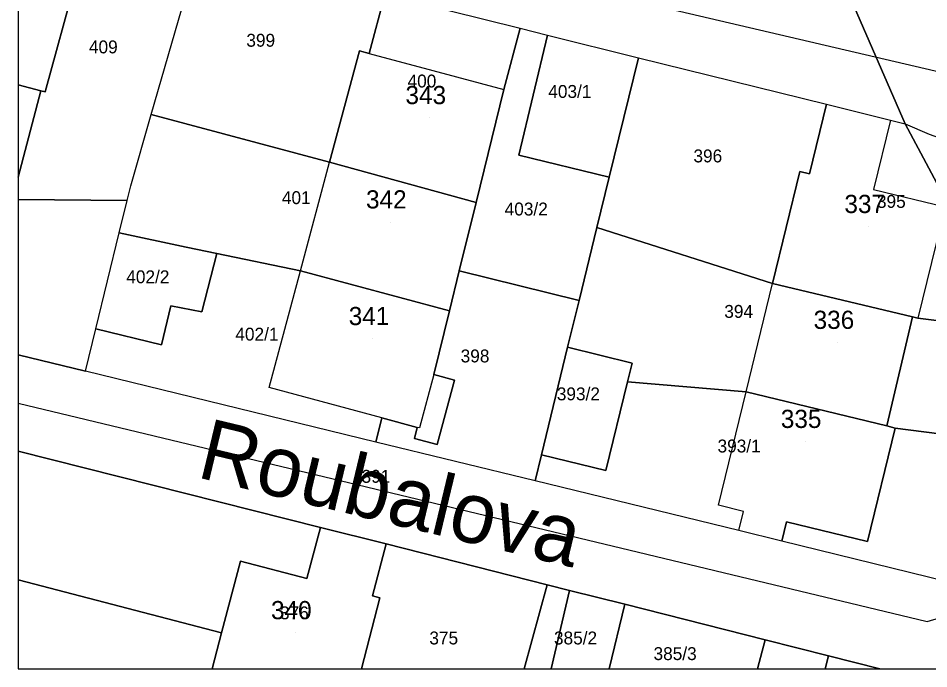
# Model space of a CAD drawing. Extents: x -873642 to -872917, y -1012962 to -1012567.
# Drawn here: x -873642.3 to -873582.3, y -1012961.7 to -1012918.8 of the extents above; entities that cross this region are included whole.
import ezdxf

# ---------------------------------------------------------------- set-up
doc = ezdxf.new("R2010")
doc.units = 0
for name, color, linetype in [('adresni_misto', 7, 'Continuous'), ('cisla_parcelni_kn', 7, 'Continuous'), ('cislo_domovni', 7, 'Continuous'), ('osy_ulic', 7, 'Continuous'), ('parcely_kn', 7, 'Continuous'), ('stavebni_objekty_bydleni', 7, 'Continuous'), ('stavebni_objekty_ostatni', 7, 'Continuous'), ('ulice', 7, 'Continuous')]:
    doc.layers.add(name, color=color, linetype=linetype)

msp = doc.modelspace()

# ---------------------------------------------------------------- linework, layer by layer
at = {"layer": 'adresni_misto'}
for p, q in [((-873615.17, -1012925.36), (-873615.17, -1012925.36)), ((-873617.77, -1012932.24), (-873617.77, -1012932.24)), ((-873586.24, -1012932.54), (-873586.24, -1012932.54)), ((-873618.91, -1012939.93), (-873618.91, -1012939.93)), ((-873588.27, -1012940.18), (-873588.27, -1012940.18)), ((-873590.43, -1012946.71), (-873590.43, -1012946.71)), ((-873624.03, -1012959.32), (-873624.03, -1012959.32))]:
    msp.add_line(p, q, dxfattribs=at)
at = {"layer": 'osy_ulic'}
for points in [[(-873642.294, -1012908.128), (-873579.23, -1012922.87)], [(-873642.294, -1012944.182), (-873582.38, -1012958.56), (-873564.82, -1012953.34)]]:
    msp.add_lwpolyline(points, dxfattribs=at)
at = {"layer": 'parcely_kn'}
for p, q in [((-873642.294, -1012910.954), (-873642.294, -1012923.197)), ((-873642.294, -1012910.954), (-873642.294, -1012923.197)), ((-873642.294, -1012923.197), (-873642.294, -1012929.279)), ((-873642.294, -1012923.197), (-873642.294, -1012929.279)), ((-873642.294, -1012929.279), (-873642.294, -1012930.754)), ((-873642.294, -1012929.279), (-873642.294, -1012930.754)), ((-873642.294, -1012930.754), (-873642.294, -1012940.985)), ((-873642.294, -1012930.754), (-873642.294, -1012940.985)), ((-873642.294, -1012940.985), (-873642.294, -1012947.334)), ((-873642.294, -1012940.985), (-873642.294, -1012947.334)), ((-873642.294, -1012947.334), (-873642.294, -1012955.815)), ((-873642.294, -1012947.334), (-873642.294, -1012955.815)), ((-873629.511, -1012961.688), (-873619.678, -1012961.688)), ((-873629.511, -1012961.688), (-873619.678, -1012961.688)), ((-873619.678, -1012961.688), (-873608.948, -1012961.688)), ((-873619.678, -1012961.688), (-873608.948, -1012961.688)), ((-873608.948, -1012961.688), (-873607.163, -1012961.688)), ((-873608.948, -1012961.688), (-873607.163, -1012961.688)), ((-873607.163, -1012961.688), (-873603.346, -1012961.688)), ((-873607.163, -1012961.688), (-873603.346, -1012961.688)), ((-873603.346, -1012961.688), (-873593.567, -1012961.688)), ((-873603.346, -1012961.688), (-873593.567, -1012961.688)), ((-873593.567, -1012961.688), (-873589.111, -1012961.688)), ((-873593.567, -1012961.688), (-873589.111, -1012961.688)), ((-873589.111, -1012961.688), (-873585.502, -1012961.688)), ((-873589.111, -1012961.688), (-873585.502, -1012961.688)), ((-873585.502, -1012961.688), (-873575.538, -1012961.688)), ((-873585.502, -1012961.688), (-873575.538, -1012961.688))]:
    msp.add_line(p, q, dxfattribs=at)
for points in [[(-873605.78, -1012857.48), (-873599.19, -1012877.96), (-873591.75, -1012899.33), (-873585.82, -1012914.89), (-873585.57, -1012916.87), (-873587.17, -1012918.1), (-873583.83, -1012925.76), (-873582.25, -1012926.45), (-873580.53, -1012927.05), (-873570.45, -1012948.46), (-873570.98, -1012949.83), (-873566.12, -1012958.98), (-873564.03, -1012959.51), (-873563.08, -1012960.39), (-873562.393, -1012961.688)], [(-873605.78, -1012857.48), (-873599.19, -1012877.96), (-873591.75, -1012899.33), (-873585.82, -1012914.89), (-873585.57, -1012916.87), (-873587.17, -1012918.1), (-873583.83, -1012925.76), (-873582.25, -1012926.45), (-873580.53, -1012927.05), (-873570.45, -1012948.46), (-873570.98, -1012949.83), (-873566.12, -1012958.98), (-873564.03, -1012959.51), (-873563.08, -1012960.39), (-873562.393, -1012961.688)], [(-873642.294, -1012910.954), (-873642.19, -1012910.98), (-873637.42, -1012912.31), (-873630.37, -1012914.2), (-873618.13, -1012917.24), (-873613.91, -1012918.29), (-873609.21, -1012919.46), (-873607.41, -1012919.91), (-873601.41, -1012921.4), (-873589.03, -1012924.47), (-873584.8, -1012925.52), (-873583.83, -1012925.76), (-873587.17, -1012918.1), (-873591.39, -1012918.13), (-873606.87, -1012914.13), (-873624.13, -1012909.67), (-873628.43, -1012908.7), (-873632.49, -1012907.8), (-873634.32, -1012907.21), (-873639.87, -1012905.77), (-873642.294, -1012905.138)], [(-873642.294, -1012910.954), (-873642.19, -1012910.98), (-873637.42, -1012912.31), (-873630.37, -1012914.2), (-873618.13, -1012917.24), (-873613.91, -1012918.29), (-873609.21, -1012919.46), (-873607.41, -1012919.91), (-873601.41, -1012921.4), (-873589.03, -1012924.47), (-873584.8, -1012925.52), (-873583.83, -1012925.76), (-873587.17, -1012918.1), (-873591.39, -1012918.13), (-873606.87, -1012914.13), (-873624.13, -1012909.67), (-873628.43, -1012908.7), (-873632.49, -1012907.8), (-873634.32, -1012907.21), (-873639.87, -1012905.77), (-873642.294, -1012905.138)], [(-873642.294, -1012923.197), (-873640.8, -1012923.59), (-873640.52, -1012923.65), (-873638.51, -1012916.34), (-873637.42, -1012912.31), (-873642.19, -1012910.98), (-873642.294, -1012910.954)], [(-873642.294, -1012923.197), (-873640.8, -1012923.59), (-873640.52, -1012923.65), (-873638.51, -1012916.34), (-873637.42, -1012912.31), (-873642.19, -1012910.98), (-873642.294, -1012910.954)], [(-873642.294, -1012930.754), (-873635.11, -1012930.82), (-873634.87, -1012929.85), (-873633.52, -1012925.14), (-873630.37, -1012914.2), (-873637.42, -1012912.31), (-873638.51, -1012916.34), (-873640.52, -1012923.65), (-873640.8, -1012923.59), (-873642.294, -1012929.279)], [(-873642.294, -1012930.754), (-873635.11, -1012930.82), (-873634.87, -1012929.85), (-873633.52, -1012925.14), (-873630.37, -1012914.2), (-873637.42, -1012912.31), (-873638.51, -1012916.34), (-873640.52, -1012923.65), (-873640.8, -1012923.59), (-873642.294, -1012929.279)], [(-873642.294, -1012929.279), (-873640.8, -1012923.59), (-873642.294, -1012923.197)], [(-873642.294, -1012929.279), (-873640.8, -1012923.59), (-873642.294, -1012923.197)], [(-873642.294, -1012940.985), (-873637.85, -1012942.07), (-873637.17, -1012939.28), (-873635.63, -1012932.95), (-873635.11, -1012930.82), (-873642.294, -1012930.754)], [(-873642.294, -1012940.985), (-873637.85, -1012942.07), (-873637.17, -1012939.28), (-873635.63, -1012932.95), (-873635.11, -1012930.82), (-873642.294, -1012930.754)], [(-873575.538, -1012961.688), (-873570.25, -1012959.15), (-873566.12, -1012958.98), (-873570.98, -1012949.83), (-873579.87, -1012956.23), (-873591.97, -1012953.27), (-873594.79, -1012952.58), (-873608.23, -1012949.3), (-873618.72, -1012946.74), (-873637.85, -1012942.07), (-873642.294, -1012940.985)], [(-873575.538, -1012961.688), (-873570.25, -1012959.15), (-873566.12, -1012958.98), (-873570.98, -1012949.83), (-873579.87, -1012956.23), (-873591.97, -1012953.27), (-873594.79, -1012952.58), (-873608.23, -1012949.3), (-873618.72, -1012946.74), (-873637.85, -1012942.07), (-873642.294, -1012940.985)], [(-873642.294, -1012947.334), (-873622.38, -1012952.37), (-873618.05, -1012953.46), (-873607.42, -1012956.15), (-873605.95, -1012956.52), (-873602.32, -1012957.43), (-873593.07, -1012959.77), (-873588.89, -1012960.83), (-873585.502, -1012961.688)], [(-873642.294, -1012955.815), (-873628.89, -1012959.32), (-873627.65, -1012954.59), (-873623.26, -1012955.74), (-873622.38, -1012952.37), (-873642.294, -1012947.334)], [(-873642.294, -1012947.334), (-873622.38, -1012952.37), (-873618.05, -1012953.46), (-873607.42, -1012956.15), (-873605.95, -1012956.52), (-873602.32, -1012957.43), (-873593.07, -1012959.77), (-873588.89, -1012960.83), (-873585.502, -1012961.688)], [(-873642.294, -1012955.815), (-873628.89, -1012959.32), (-873627.65, -1012954.59), (-873623.26, -1012955.74), (-873622.38, -1012952.37), (-873642.294, -1012947.334)], [(-873619.678, -1012961.688), (-873618.46, -1012957), (-873618.94, -1012956.87), (-873618.05, -1012953.46), (-873622.38, -1012952.37), (-873623.26, -1012955.74), (-873627.65, -1012954.59), (-873628.89, -1012959.32), (-873629.511, -1012961.688)], [(-873619.678, -1012961.688), (-873618.46, -1012957), (-873618.94, -1012956.87), (-873618.05, -1012953.46), (-873622.38, -1012952.37), (-873623.26, -1012955.74), (-873627.65, -1012954.59), (-873628.89, -1012959.32), (-873629.511, -1012961.688)], [(-873608.948, -1012961.688), (-873607.42, -1012956.15), (-873618.05, -1012953.46), (-873618.94, -1012956.87), (-873618.46, -1012957), (-873619.678, -1012961.688)], [(-873608.948, -1012961.688), (-873607.42, -1012956.15), (-873618.05, -1012953.46), (-873618.94, -1012956.87), (-873618.46, -1012957), (-873619.678, -1012961.688)], [(-873642.294, -1012955.815), (-873642.294, -1012961.688), (-873629.511, -1012961.688)], [(-873629.511, -1012961.688), (-873628.89, -1012959.32), (-873642.294, -1012955.815)], [(-873642.294, -1012955.815), (-873642.294, -1012961.688), (-873629.511, -1012961.688)], [(-873629.511, -1012961.688), (-873628.89, -1012959.32), (-873642.294, -1012955.815)], [(-873607.163, -1012961.688), (-873605.95, -1012956.52), (-873607.42, -1012956.15), (-873608.948, -1012961.688)], [(-873607.163, -1012961.688), (-873605.95, -1012956.52), (-873607.42, -1012956.15), (-873608.948, -1012961.688)], [(-873603.346, -1012961.688), (-873602.32, -1012957.43), (-873605.95, -1012956.52), (-873607.163, -1012961.688)], [(-873603.346, -1012961.688), (-873602.32, -1012957.43), (-873605.95, -1012956.52), (-873607.163, -1012961.688)], [(-873593.567, -1012961.688), (-873593.07, -1012959.77), (-873602.32, -1012957.43), (-873603.346, -1012961.688)], [(-873593.567, -1012961.688), (-873593.07, -1012959.77), (-873602.32, -1012957.43), (-873603.346, -1012961.688)], [(-873589.111, -1012961.688), (-873588.89, -1012960.83), (-873593.07, -1012959.77), (-873593.567, -1012961.688)], [(-873589.111, -1012961.688), (-873588.89, -1012960.83), (-873593.07, -1012959.77), (-873593.567, -1012961.688)], [(-873585.502, -1012961.688), (-873588.89, -1012960.83), (-873589.111, -1012961.688)], [(-873585.502, -1012961.688), (-873588.89, -1012960.83), (-873589.111, -1012961.688)]]:
    msp.add_lwpolyline(points, dxfattribs=at)
for points in [[(-873633.52, -1012925.14), (-873630.37, -1012914.2), (-873618.13, -1012917.24), (-873619.17, -1012921.12), (-873619.8, -1012920.95), (-873621.77, -1012928.29)], [(-873633.52, -1012925.14), (-873630.37, -1012914.2), (-873618.13, -1012917.24), (-873619.17, -1012921.12), (-873619.8, -1012920.95), (-873621.77, -1012928.29)], [(-873619.8, -1012920.95), (-873619.17, -1012921.12), (-873618.13, -1012917.24), (-873613.91, -1012918.29), (-873609.21, -1012919.46), (-873610.29, -1012923.5), (-873612.11, -1012930.94), (-873621.77, -1012928.29)], [(-873619.8, -1012920.95), (-873619.17, -1012921.12), (-873618.13, -1012917.24), (-873613.91, -1012918.29), (-873609.21, -1012919.46), (-873610.29, -1012923.5), (-873612.11, -1012930.94), (-873621.77, -1012928.29)], [(-873610.29, -1012923.5), (-873609.21, -1012919.46), (-873607.41, -1012919.91), (-873609.3, -1012927.83), (-873603.34, -1012929.28), (-873604.15, -1012932.59), (-873605.32, -1012937.4), (-873613.22, -1012935.46), (-873612.11, -1012930.94)], [(-873610.29, -1012923.5), (-873609.21, -1012919.46), (-873607.41, -1012919.91), (-873609.3, -1012927.83), (-873603.34, -1012929.28), (-873604.15, -1012932.59), (-873605.32, -1012937.4), (-873613.22, -1012935.46), (-873612.11, -1012930.94)], [(-873607.41, -1012919.91), (-873601.41, -1012921.4), (-873603.34, -1012929.28), (-873609.3, -1012927.83)], [(-873607.41, -1012919.91), (-873601.41, -1012921.4), (-873603.34, -1012929.28), (-873609.3, -1012927.83)], [(-873601.41, -1012921.4), (-873589.03, -1012924.47), (-873590.14, -1012929.06), (-873590.77, -1012928.9), (-873592.57, -1012936.29), (-873604.15, -1012932.59), (-873603.34, -1012929.28)], [(-873601.41, -1012921.4), (-873589.03, -1012924.47), (-873590.14, -1012929.06), (-873590.77, -1012928.9), (-873592.57, -1012936.29), (-873604.15, -1012932.59), (-873603.34, -1012929.28)], [(-873590.77, -1012928.9), (-873590.14, -1012929.06), (-873589.03, -1012924.47), (-873584.8, -1012925.52), (-873583.83, -1012925.76), (-873576.56, -1012939.38), (-873582.99, -1012938.57), (-873583.35, -1012938.49), (-873592.57, -1012936.29)], [(-873590.77, -1012928.9), (-873590.14, -1012929.06), (-873589.03, -1012924.47), (-873584.8, -1012925.52), (-873583.83, -1012925.76), (-873576.56, -1012939.38), (-873582.99, -1012938.57), (-873583.35, -1012938.49), (-873592.57, -1012936.29)], [(-873635.11, -1012930.82), (-873634.87, -1012929.85), (-873633.52, -1012925.14), (-873621.77, -1012928.29), (-873612.11, -1012930.94), (-873613.22, -1012935.46), (-873613.86, -1012938.08), (-873623.69, -1012935.44), (-873629.2, -1012934.3), (-873631.23, -1012933.88), (-873635.63, -1012932.95)], [(-873635.11, -1012930.82), (-873634.87, -1012929.85), (-873633.52, -1012925.14), (-873621.77, -1012928.29), (-873612.11, -1012930.94), (-873613.22, -1012935.46), (-873613.86, -1012938.08), (-873623.69, -1012935.44), (-873629.2, -1012934.3), (-873631.23, -1012933.88), (-873635.63, -1012932.95)], [(-873583.83, -1012925.76), (-873582.25, -1012926.45), (-873580.53, -1012927.05), (-873570.45, -1012948.46), (-873570.98, -1012949.83), (-873572.29, -1012947.38), (-873576.56, -1012939.38)], [(-873583.83, -1012925.76), (-873582.25, -1012926.45), (-873580.53, -1012927.05), (-873570.45, -1012948.46), (-873570.98, -1012949.83), (-873572.29, -1012947.38), (-873576.56, -1012939.38)], [(-873605.32, -1012937.4), (-873604.15, -1012932.59), (-873592.57, -1012936.29), (-873583.35, -1012938.49), (-873585.05, -1012945.68), (-873594.31, -1012943.43), (-873602.13, -1012942.76), (-873601.83, -1012941.54), (-873606.08, -1012940.49)], [(-873605.32, -1012937.4), (-873604.15, -1012932.59), (-873592.57, -1012936.29), (-873583.35, -1012938.49), (-873585.05, -1012945.68), (-873594.31, -1012943.43), (-873602.13, -1012942.76), (-873601.83, -1012941.54), (-873606.08, -1012940.49)], [(-873631.23, -1012933.88), (-873629.2, -1012934.3), (-873630.2, -1012938.16), (-873632.23, -1012937.75), (-873632.86, -1012940.33), (-873637.17, -1012939.28), (-873635.63, -1012932.95)], [(-873631.23, -1012933.88), (-873629.2, -1012934.3), (-873630.2, -1012938.16), (-873632.23, -1012937.75), (-873632.86, -1012940.33), (-873637.17, -1012939.28), (-873635.63, -1012932.95)], [(-873637.17, -1012939.28), (-873632.86, -1012940.33), (-873632.23, -1012937.75), (-873630.2, -1012938.16), (-873629.2, -1012934.3), (-873623.69, -1012935.44), (-873613.86, -1012938.08), (-873614.89, -1012942.29), (-873613.54, -1012942.65), (-873614.69, -1012946.9), (-873616.18, -1012946.5), (-873615.99, -1012945.77), (-873618.33, -1012945.14), (-873618.72, -1012946.74), (-873637.85, -1012942.07)], [(-873637.17, -1012939.28), (-873632.86, -1012940.33), (-873632.23, -1012937.75), (-873630.2, -1012938.16), (-873629.2, -1012934.3), (-873623.69, -1012935.44), (-873613.86, -1012938.08), (-873614.89, -1012942.29), (-873613.54, -1012942.65), (-873614.69, -1012946.9), (-873616.18, -1012946.5), (-873615.99, -1012945.77), (-873618.33, -1012945.14), (-873618.72, -1012946.74), (-873637.85, -1012942.07)], [(-873615.99, -1012945.77), (-873616.18, -1012946.5), (-873614.69, -1012946.9), (-873613.54, -1012942.65), (-873614.89, -1012942.29), (-873613.86, -1012938.08), (-873613.22, -1012935.46), (-873605.32, -1012937.4), (-873606.08, -1012940.49), (-873607.81, -1012947.58), (-873608.23, -1012949.3), (-873618.72, -1012946.74), (-873618.33, -1012945.14)], [(-873615.99, -1012945.77), (-873616.18, -1012946.5), (-873614.69, -1012946.9), (-873613.54, -1012942.65), (-873614.89, -1012942.29), (-873613.86, -1012938.08), (-873613.22, -1012935.46), (-873605.32, -1012937.4), (-873606.08, -1012940.49), (-873607.81, -1012947.58), (-873608.23, -1012949.3), (-873618.72, -1012946.74), (-873618.33, -1012945.14)], [(-873572.29, -1012947.38), (-873584.49, -1012945.82), (-873585.05, -1012945.68), (-873583.35, -1012938.49), (-873582.99, -1012938.57), (-873576.56, -1012939.38)], [(-873572.29, -1012947.38), (-873584.49, -1012945.82), (-873585.05, -1012945.68), (-873583.35, -1012938.49), (-873582.99, -1012938.57), (-873576.56, -1012939.38)], [(-873606.08, -1012940.49), (-873601.83, -1012941.54), (-873602.13, -1012942.76), (-873603.56, -1012948.61), (-873607.81, -1012947.58)], [(-873606.08, -1012940.49), (-873601.83, -1012941.54), (-873602.13, -1012942.76), (-873603.56, -1012948.61), (-873607.81, -1012947.58)], [(-873607.81, -1012947.58), (-873603.56, -1012948.61), (-873602.13, -1012942.76), (-873594.31, -1012943.43), (-873585.05, -1012945.68), (-873584.49, -1012945.82), (-873586.32, -1012953.3), (-873591.66, -1012952), (-873591.97, -1012953.27), (-873594.79, -1012952.58), (-873608.23, -1012949.3)], [(-873607.81, -1012947.58), (-873603.56, -1012948.61), (-873602.13, -1012942.76), (-873594.31, -1012943.43), (-873585.05, -1012945.68), (-873584.49, -1012945.82), (-873586.32, -1012953.3), (-873591.66, -1012952), (-873591.97, -1012953.27), (-873594.79, -1012952.58), (-873608.23, -1012949.3)], [(-873586.32, -1012953.3), (-873584.49, -1012945.82), (-873572.29, -1012947.38), (-873570.98, -1012949.83), (-873579.87, -1012956.23), (-873591.97, -1012953.27), (-873591.66, -1012952)], [(-873586.32, -1012953.3), (-873584.49, -1012945.82), (-873572.29, -1012947.38), (-873570.98, -1012949.83), (-873579.87, -1012956.23), (-873591.97, -1012953.27), (-873591.66, -1012952)]]:
    msp.add_lwpolyline(points, close=True, dxfattribs=at)
at = {"layer": 'stavebni_objekty_bydleni'}
for p, q in [((-873642.294, -1012915.359), (-873642.294, -1012923.197)), ((-873642.294, -1012923.197), (-873642.294, -1012929.279)), ((-873629.511, -1012961.688), (-873619.678, -1012961.688)), ((-873593.567, -1012961.688), (-873589.111, -1012961.688))]:
    msp.add_line(p, q, dxfattribs=at)
for points in [[(-873642.294, -1012923.197), (-873640.8, -1012923.59), (-873640.52, -1012923.65), (-873638.51, -1012916.34), (-873642.294, -1012915.359)], [(-873642.294, -1012929.279), (-873640.8, -1012923.59), (-873642.294, -1012923.197)], [(-873619.678, -1012961.688), (-873618.46, -1012957), (-873618.94, -1012956.87), (-873618.05, -1012953.46), (-873622.38, -1012952.37), (-873623.26, -1012955.74), (-873627.65, -1012954.59), (-873628.89, -1012959.32), (-873629.511, -1012961.688)], [(-873589.111, -1012961.688), (-873588.89, -1012960.83), (-873593.07, -1012959.77), (-873593.567, -1012961.688)]]:
    msp.add_lwpolyline(points, dxfattribs=at)
for points in [[(-873621.77, -1012928.29), (-873619.8, -1012920.95), (-873619.17, -1012921.12), (-873614.97, -1012922.24), (-873610.29, -1012923.5), (-873612.11, -1012930.94)], [(-873590.77, -1012928.9), (-873590.14, -1012929.06), (-873589.03, -1012924.47), (-873584.8, -1012925.52), (-873585.92, -1012930.09), (-873581.21, -1012931.24), (-873582.99, -1012938.57), (-873583.35, -1012938.49), (-873592.57, -1012936.29)], [(-873621.77, -1012928.29), (-873612.11, -1012930.94), (-873613.22, -1012935.46), (-873613.86, -1012938.08), (-873623.69, -1012935.44)], [(-873615.99, -1012945.77), (-873618.33, -1012945.14), (-873625.76, -1012943.15), (-873623.69, -1012935.44), (-873613.86, -1012938.08), (-873614.89, -1012942.29), (-873615.84, -1012945.81)], [(-873592.57, -1012936.29), (-873583.35, -1012938.49), (-873585.05, -1012945.68), (-873594.31, -1012943.43)], [(-873586.32, -1012953.3), (-873591.66, -1012952), (-873591.97, -1012953.27), (-873594.79, -1012952.58), (-873594.48, -1012951.32), (-873596.13, -1012950.91), (-873594.31, -1012943.43), (-873585.05, -1012945.68), (-873584.49, -1012945.82)]]:
    msp.add_lwpolyline(points, close=True, dxfattribs=at)
at = {"layer": 'stavebni_objekty_ostatni'}
for points in [[(-873637.17, -1012939.28), (-873635.63, -1012932.95), (-873631.23, -1012933.88), (-873629.2, -1012934.3), (-873630.2, -1012938.16), (-873632.23, -1012937.75), (-873632.86, -1012940.33)], [(-873606.08, -1012940.49), (-873601.83, -1012941.54), (-873602.13, -1012942.76), (-873603.56, -1012948.61), (-873607.81, -1012947.58)]]:
    msp.add_lwpolyline(points, close=True, dxfattribs=at)

# ---------------------------------------------------------------- texts
at = {"layer": 'cisla_parcelni_kn'}
for s, p in [('399', (-873627.258, -1012920.675)), ('399', (-873627.258, -1012920.675)), ('409', (-873637.633, -1012921.113)), ('409', (-873637.633, -1012921.113)), ('400', (-873616.633, -1012923.363)), ('400', (-873616.633, -1012923.363)), ('403/1', (-873607.358, -1012924.05)), ('403/1', (-873607.358, -1012924.05)), ('396', (-873597.79, -1012928.3)), ('396', (-873597.79, -1012928.3)), ('401', (-873624.915, -1012931.05)), ('401', (-873624.915, -1012931.05)), ('395', (-873585.696, -1012931.3)), ('395', (-873585.696, -1012931.3)), ('403/2', (-873610.233, -1012931.8)), ('403/2', (-873610.233, -1012931.8)), ('402/2', (-873635.171, -1012936.269)), ('402/2', (-873635.171, -1012936.269)), ('394', (-873595.758, -1012938.55)), ('394', (-873595.758, -1012938.55)), ('402/1', (-873627.983, -1012940.05)), ('402/1', (-873627.983, -1012940.05)), ('398', (-873613.133, -1012941.488)), ('398', (-873613.133, -1012941.488)), ('393/2', (-873606.796, -1012943.988)), ('393/2', (-873606.796, -1012943.988)), ('393/1', (-873596.202, -1012947.425)), ('393/1', (-873596.202, -1012947.425)), ('391', (-873619.665, -1012949.425)), ('391', (-873619.665, -1012949.425)), ('376', (-873625.04, -1012958.425)), ('376', (-873625.04, -1012958.425)), ('375', (-873615.196, -1012960.081)), ('375', (-873615.196, -1012960.081)), ('385/2', (-873606.983, -1012960.081)), ('385/2', (-873606.983, -1012960.081)), ('385/3', (-873600.421, -1012961.113)), ('385/3', (-873600.421, -1012961.113))]:
    msp.add_text(s, height=0.85, dxfattribs=at).set_placement(p)
at = {"layer": 'cislo_domovni'}
for s, p in [('343', (-873616.77, -1012924.46)), ('342', (-873619.37, -1012931.34)), ('337', (-873587.84, -1012931.64)), ('341', (-873620.51, -1012939.03)), ('336', (-873589.87, -1012939.28)), ('335', (-873592.03, -1012945.81)), ('340', (-873625.63, -1012958.42))]:
    msp.add_text(s, height=1.2, dxfattribs=at).set_placement(p)
at = {"layer": 'ulice'}
msp.add_text('Roubalova', height=4, rotation=346.50508, dxfattribs=at).set_placement((-873630.613, -1012949.041))

doc.saveas('drawing.dxf')
